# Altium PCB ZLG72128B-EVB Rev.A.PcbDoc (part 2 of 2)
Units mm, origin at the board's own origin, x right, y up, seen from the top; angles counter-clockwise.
Board outline 130 x 80 mm, 2 copper layers (Top Layer, Bottom Layer); 109 components, 70 nets, 433 pads, 399 vias.
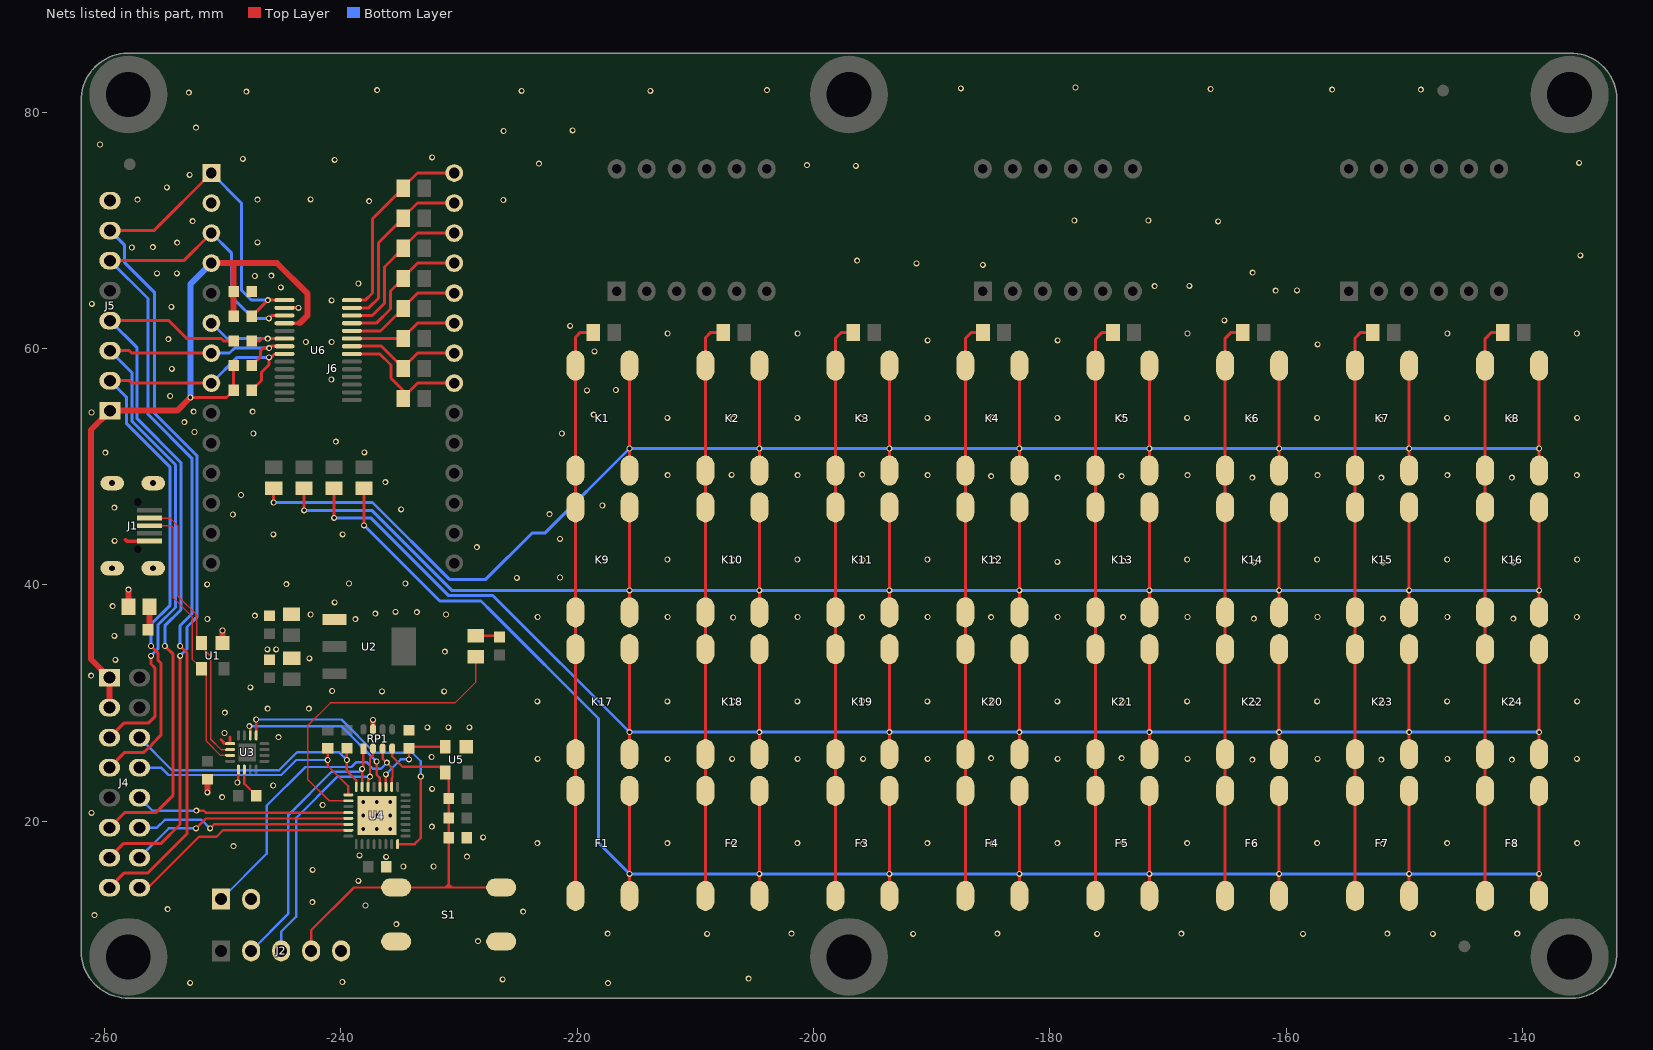
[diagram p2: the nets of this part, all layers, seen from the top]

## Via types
v1: diameter 0.508, hole 0.305, Top Layer to Bottom Layer, tented both sides, 399 vias

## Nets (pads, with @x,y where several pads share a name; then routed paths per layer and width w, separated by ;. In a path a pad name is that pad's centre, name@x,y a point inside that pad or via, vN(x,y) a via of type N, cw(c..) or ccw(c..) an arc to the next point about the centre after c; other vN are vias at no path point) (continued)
GND: C1.2 C2.1 C3.1 C4.2 C5.2 C7.1 C11.1 C12.1 J1.5 J1.6 J1.7 J1.8 J1.9 J2.5 J3.2 J5.8 J6.2 LED3.2 R7.1 RP1.7 S1.1 S1.4 U1.1 U2.1 U3.1 U3.13 U4.33 U5.1 U6.2 | length 10.3
  Top Layer w0.203: v1(-248.764,23.263) -248.676,23.351 U3.1@-248.676,24.353
  Top Layer w0.254: -250.161,26.883 -249.831,26.553 U3.13@-249.376,26.553 -249.376,27.128
  Top Layer w0.305: -258.238,43.811 -258.127,43.7 J1.5@-256.201,43.7 ; U6.2@-244.781,63.439 v1(-243.589,63.439)
  Top Layer w0.406: RP1.7@-237.289,27.765 v1(-237.289,28.565)
  Top Layer w0.508: LED3.2@-257.984,38.147 v1(-257.984,39.595) ; v1(-251.306,22.427) C5.2@-251.306,23.529 ; U1.1@-250.021,35.074 v1(-250.021,36.128)
  other v1: -217.399,6.274 -252.755,6.299 -239.878,6.375 -226.314,6.604 -205.486,6.655 -228.397,9.83 -208.997,10.447 -191.569,10.447 -175.997,10.447 -158.569,10.447 -147.569,10.447 -217.432,10.472 -201.86,10.472 -184.432,10.472 -168.86,10.472 -151.432,10.472 -140.432,10.472 -235.306,11.278 -260.858,12.04 -224.569,12.326 -254.66,12.548 -237.918,12.849 -242.414,13.128 -238.528,14.931 -242.388,15.871 -234.718,16.151 -232.152,16.151 -236.179,16.969 -229.333,16.989 -238.426,17.089 -249.098,17.882 -195.83,18.081 -184.832,18.081 -162.734,18.081 -151.812,18.081 -140.763,18.081 -206.752,18.106 -223.367,18.135 -212.367,18.135 -201.367,18.135 -190.367,18.135 -179.367,18.135 -168.367,18.135 -157.367,18.135 -146.367,18.135 -135.36,18.135 -173.783,18.208 -227.961,18.614 -238.096,19.326 -236.953,19.326 -235.81,19.326 -232.305,19.529 -238.096,20.469 -236.953,20.469 -235.81,20.469 -261.112,20.701 -241.554,21.361 -238.096,21.612 -236.953,21.612 -235.81,21.612 -250.063,22.022 -232.287,22.729 -245.745,23.012 -162.861,25.193 -151.939,25.193 -140.89,25.193 -223.342,25.272 -212.342,25.272 -206.879,25.269 -201.342,25.272 -195.805,25.269 -190.342,25.272 -179.342,25.272 -168.342,25.272 -157.342,25.272 -146.342,25.272 -135.385,25.272 -184.959,25.32 -173.91,25.32 -232.33,25.422 -245.284,27.098 -249.856,27.454 -232.686,27.936 -230.908,27.936 -229.13,27.936 -249.831,29.181 -246.198,29.511 -242.719,29.511 -162.795,29.976 -151.873,29.976 -140.824,29.976 -173.844,30.103 -206.778,30.121 -223.367,30.135 -212.367,30.135 -201.367,30.135 -195.881,30.146 -190.367,30.135 -184.832,30.146 -179.367,30.135 -168.367,30.135 -157.367,30.135 -146.367,30.135 -135.36,30.135 -236.521,30.984 -231.263,30.984 -240.737,31.01 -247.672,31.314 -261.137,32.309 -259.102,33.639 -242.668,33.766 -231.212,34.337 -246.224,34.54 -245.487,34.54 -259.178,35.683 -238.785,37.084 -251.304,37.106 -162.734,37.131 -151.812,37.131 -140.763,37.131 -206.803,37.233 -195.881,37.258 -184.959,37.258 -173.783,37.258 -223.342,37.272 -212.342,37.272 -201.342,37.272 -190.342,37.272 -179.342,37.272 -168.342,37.272 -157.342,37.272 -146.342,37.272 -135.385,37.272 -247.291,37.385 -242.566,37.487 -231.111,37.487 -237.08,37.563 -233.575,37.69 -235.378,37.715 -259.33,38.198 -240.538,38.506 -251.329,40.027 -244.624,40.052 -239.315,40.103 -234.54,40.103 -225.116,40.585 -221.459,40.611 -162.73,41.882 -151.808,41.882 -140.759,41.882 -179.367,41.932 -173.779,42.009 -184.705,42.084 -206.803,42.109 -195.844,42.103 -212.367,42.135 -201.367,42.135 -190.367,42.135 -168.367,42.135 -157.367,42.135 -146.367,42.135 -135.36,42.135 -228.495,43.176 -259.152,43.71 -221.459,43.887 -245.716,44.268 -239.848,44.268 -249.145,45.945 -222.348,45.97 -234.895,46.377 -259.178,46.529 -217.877,46.707 -248.459,47.596 -236.242,48.688 -179.342,49.069 -162.861,49.069 -151.939,49.069 -140.89,49.069 -184.959,49.196 -173.91,49.196 -212.342,49.272 -201.342,49.272 -190.342,49.272 -168.342,49.272 -157.342,49.272 -146.342,49.272 -135.385,49.272 -206.93,49.298 -195.881,49.323 -259.94,51.177 -238.02,51.203 -240.433,52.117 -247.418,52.803 -221.306,52.803 -252.396,52.93 -253.249,53.768 -162.922,53.976 -152,53.976 -140.951,53.976 -206.803,54.098 -195.971,54.099 -173.971,54.103 -212.367,54.135 -201.367,54.135 -190.367,54.135 -179.367,54.135 -168.367,54.135 -157.367,54.135 -146.367,54.135 -135.36,54.135 -184.832,54.149 -218.614,54.403 -261.112,54.585 -252.472,54.657 -247.468,54.657 -254.457,55.982 -219.173,56.46 -216.734,56.486 -240.814,57.375 -254.305,58.268 -218.538,59.762 -157.324,60.347 -242.973,60.55 -240.788,60.55 -190.342,60.688 -179.342,60.688 -254.61,60.782 -212.342,61.272 -201.342,61.272 -168.342,61.272 -146.342,61.272 -135.385,61.272 -220.595,61.921 -165.223,62.379 -254.356,63.525 -261.087,63.779 -240.788,64.08 -160.88,64.893 -159.076,64.919 -245.081,65.173 -171.116,65.274 -168.195,65.3 -238.528,65.503 -247.279,66.138 -245.894,66.163 -255.571,66.366 -253.895,66.366 -162.836,66.417 -185.67,67.078 -191.284,67.205 -196.313,67.433 -135.099,67.89 -257.705,68.551 -255.927,68.576 -253.869,68.957 -247.062,68.983 -165.757,70.761 -252.548,70.786 -177.923,70.837 -171.649,70.837 -237.613,72.462 -226.259,72.564 -257.222,72.589 -247.062,72.589 -242.566,72.615 -254.733,73.631 -252.802,74.698 -196.414,75.46 -200.555,75.51 -223.237,75.637 -135.2,75.714 -240.534,75.968 -248.307,76.044 -232.279,76.171 -260.397,77.263 -226.234,78.406 -220.392,78.457 -252.269,78.685 -252.88,81.66 -248.002,81.733 -224.71,81.81 -213.813,81.81 -236.927,81.86 -203.933,81.86 -156.105,81.911 -148.586,81.911 -166.392,81.962 -187.524,82.013 -177.822,82.089
I2C0_SCL: J4.7 J5.2 J6.8 R15.1 U6.8 | length 57.7
  Top Layer w0.254: J4.7@-259.595,24.52 -258.299,25.816 -256.688,25.816 -256.397,26.107 ccw(c-256.905,27.06) -255.952,26.552 -255.245,27.259 -255.245,33.376 -255.495,33.626 -255.495,34.235 v1(-256.079,34.82) ; J5.2@-259.543,57.273 -257.908,57.273 -257.705,57.07 J6.8@-250.963,57.07 ; R15.1@-247.551,56.46 -246.72,57.291 -246.72,57.995 -246.085,58.63 v1(-246.085,59.257) ; v1@-245.907,59.257 -245.625,59.539 U6.8@-244.781,59.539
  Bottom Layer w0.254: J5.2@-259.543,57.273 -258.162,55.892 -258.162,53.666 -254.453,49.958 -254.453,38.274 -256.079,36.648 v1(-256.079,34.82) ; J6.8@-250.963,57.07 -248.776,59.257 v1(-246.085,59.257)
I2C0_SDA: J4.5 J5.3 J6.7 R16.1 U6.7 | length 56.3
  Top Layer w0.254: J4.5@-259.595,27.06 -258.376,28.279 -256.302,28.279 -255.753,28.829 -255.753,32.969 -256.079,33.296 v1(-256.079,33.981) ; J5.3@-259.543,59.813 -257.913,59.813 -257.71,59.61 J6.7@-250.963,59.61 ; R16.1@-247.551,58.55 -246.808,59.293 -246.808,59.807 -246.579,60.036 v1(-246.078,60.036) -245.924,60.189 U6.7@-244.781,60.189
  Bottom Layer w0.254: J5.3@-259.543,59.813 -257.705,57.975 -257.705,53.856 -253.996,50.147 -253.996,38.085 -255.495,36.586 -255.495,34.566 v1(-256.079,33.981) ; J6.7@-250.963,59.61 -249.424,59.61 -248.999,60.036 v1(-246.078,60.036)
IIC/SPI: J4.15 J5.6 J6.3 U6.3 | length 81.5
  Top Layer w0.254: J4.15@-259.595,14.36 -258.338,15.617 -256.333,15.617 -253.031,18.919 -253.031,34.235 v1(-253.615,34.82) ; J5.6@-259.543,67.433 -253.3,67.433 J6.3@-250.963,69.77 ; v1(-246.097,62.556) -245.864,62.789 U6.3@-244.781,62.789
  Bottom Layer w0.254: J5.6@-259.543,67.433 -256.333,64.223 -256.333,54.424 -252.625,50.716 -252.625,37.516 -253.615,36.526 v1(-253.615,34.82) ; J6.3@-250.963,69.77 -249.246,68.053 -249.246,64.36 -247.443,62.556 v1(-246.097,62.556)
ISP: J3.1 RP1.3 U4.2 | length 25.2
  Top Layer w0.203: RP1.3@-236.477,26.139 -236.477,25.301 v1(-236.111,24.936) -235.632,24.456 -235.632,23.717 ; U4.2@-235.703,22.894 -235.703,23.646
  Bottom Layer w0.203: J3.1@-250.135,13.382 -246.275,17.243 -246.275,21.307 -243.004,24.577 -239.093,24.577 -238.68,24.99 -237.842,24.99 -237.283,24.431 -236.616,24.431 v1(-236.111,24.936)
J_NRST: C9.1 C11.2 J2.4 R6.1 RP1.4 S1.2 S1.3 U5.3 | length 35.9
  Top Layer w0.203: J2.4@-242.515,9.013 -242.515,10.766 -238.909,14.373 -237.715,14.373 ; -237.943,14.373 S1.3@-235.327,14.373 -230.882,14.373 ; RP1.4@-235.664,26.139 -235.664,25.479 -234.768,24.583 -231.657,24.583 U5.3@-231.174,24.101 -230.882,23.809 C9.1@-230.882,21.916 R6.1@-230.882,20.253 C11.2@-230.882,18.589 -230.882,14.779 -230.882,14.652 ; -231.162,14.373 -230.882,14.652 ; -230.603,14.373 -230.882,14.652 ; S1.2@-226.437,14.373 -230.882,14.373 ; -230.882,14.373 -230.882,14.652
KEY: J6.6 R17.2 U6.6 | length 8.3
  Top Layer w0.254: R17.2@-247.551,60.639 -246.878,60.639 -246.678,60.839 v1(-246.195,60.839) ; v1@-246.302,60.839 v1(-246.195,60.839) ; U6.6@-244.781,60.839 v1(-246.195,60.839)
  Bottom Layer w0.254: J6.6@-250.963,62.15 -249.652,60.839 v1(-246.195,60.839)
KEY_INT: J4.11 J5.4 R17.1 | length 61.2
  Top Layer w0.254: J4.11@-259.595,19.44 -258.325,20.71 -255.685,20.71 -254.203,22.192 -254.203,34.112 v1(-254.911,34.82) ; J5.4@-259.543,62.353 -254.555,62.353 -253.056,60.855 -250.135,60.855 -249.92,60.639 R17.1@-249.075,60.639
  Bottom Layer w0.254: J5.4@-259.543,62.353 -257.247,60.058 -257.247,54.045 -253.539,50.337 -253.539,37.895 -254.911,36.524 v1(-254.911,34.82)
LED0: LED0.2 U4.10 | length 26.6
  Top Layer w0.127: U4.10@-239.378,21.719 -240.997,21.719 -242.82,23.542 -242.82,28.063 -240.89,29.994 -230.349,29.994 -228.571,31.772 LED0.2@-228.571,33.905
NetF1_1: F1.1 F1.4 F2.1 F2.4 F3.1 F3.4 F4.1 F4.4 F5.1 F5.4 F6.1 F6.4 F7.1 F7.4 F8.1 F8.4 R31.2 | length 193.3
  Top Layer w0.254: v1(-238.045,45.03) R31.2@-238.045,48.155 -238.045,46.961 ; F1.4@-215.578,13.664 v1(-215.578,15.533) F1.1@-215.578,22.554 ; F2.4@-204.578,13.664 v1(-204.578,15.533) F2.1@-204.578,22.554 ; F3.4@-193.578,13.664 v1(-193.578,15.533) F3.1@-193.578,22.554 ; F4.4@-182.578,13.664 v1(-182.578,15.533) F4.1@-182.578,22.554 ; F5.4@-171.578,13.664 v1(-171.578,15.533) F5.1@-171.578,22.554 ; F6.4@-160.578,13.664 v1(-160.578,15.533) F6.1@-160.578,22.554 ; F7.4@-149.578,13.664 v1(-149.578,15.533) F7.1@-149.578,22.554 ; F8.4@-138.578,13.664 v1(-138.578,15.533) F8.1@-138.578,22.554
  Bottom Layer w0.254: v1(-238.045,45.03) -231.633,38.618 -228.153,38.618 -227.199,37.664 -218.208,28.673 -218.208,18.163 v1(-215.578,15.533) v1(-204.578,15.533) v1(-193.578,15.533) v1(-182.578,15.533) v1(-171.578,15.533) v1(-160.578,15.533) v1(-149.578,15.533) v1(-138.578,15.533)
NetF1_2: F1.2 F1.3 K1.2 K1.3 K9.2 K9.3 K17.2 K17.3 R20.1 | length 49
  Top Layer w0.254: F1.3@-220.15,13.664 F1.2@-220.15,22.554 K17.3@-220.15,25.664 K17.2@-220.15,34.554 K9.3@-220.15,37.664 K9.2@-220.15,46.554 K1.3@-220.15,49.664 K1.2@-220.15,58.554 -220.15,60.956 -219.743,61.363 R20.1@-218.651,61.363
NetF2_2: F2.2 F2.3 K2.2 K2.3 K10.2 K10.3 K18.2 K18.3 R21.1 | length 49.7
  Top Layer w0.254: F2.3@-209.15,13.664 F2.2@-209.15,22.554 K18.3@-209.15,25.664 K18.2@-209.15,34.554 K10.3@-209.15,37.664 K10.2@-209.15,46.554 K2.3@-209.15,49.664 K2.2@-209.15,58.554 ; K2.2@-209.15,59.048 K2.2@-209.15,58.554 ; -209.15,60.51 -209.15,60.22 ; R21.1@-207.651,61.363 -208.704,61.363 -209.15,60.917 -209.15,60.22 ; K2.2@-209.15,58.554 -209.15,60.22
NetF3_2: F3.2 F3.3 K3.2 K3.3 K11.2 K11.3 K19.2 K19.3 R22.1 | length 49.5
  Top Layer w0.254: F3.3@-198.15,13.664 F3.2@-198.15,22.554 K19.3@-198.15,25.664 K19.2@-198.15,34.554 K11.3@-198.15,37.664 K11.2@-198.15,46.554 K3.3@-198.15,49.664 K3.2@-198.15,58.554 ; K3.2@-198.15,59.11 K3.2@-198.15,58.554 ; R22.1@-196.652,61.363 -197.639,61.363 -198.15,60.852 K3.2@-198.15,58.554
NetF4_2: F4.2 F4.3 K4.2 K4.3 K12.2 K12.3 K20.2 K20.3 R23.1 | length 49.5
  Top Layer w0.254: F4.3@-187.15,13.664 F4.2@-187.15,22.554 K20.3@-187.15,25.664 K20.2@-187.15,34.554 K12.3@-187.15,37.664 K12.2@-187.15,46.554 K4.3@-187.15,49.664 K4.2@-187.15,58.554 ; K4.2@-187.15,59.121 K4.2@-187.15,58.554 ; R23.1@-185.652,61.363 -186.624,61.363 -187.15,60.837 K4.2@-187.15,58.554
NetF5_2: F5.2 F5.3 K5.2 K5.3 K13.2 K13.3 K21.2 K21.3 R24.1 | length 48.8
  Top Layer w0.254: F5.3@-176.15,13.664 F5.2@-176.15,22.554 K21.3@-176.15,25.664 K21.2@-176.15,34.554 K13.3@-176.15,37.664 K13.2@-176.15,46.554 K5.3@-176.15,49.664 K5.2@-176.15,58.554 -176.15,60.765 -175.552,61.363 R24.1@-174.652,61.363
NetF6_2: F6.2 F6.3 K6.2 K6.3 K14.2 K14.3 K22.2 K22.3 R25.1 | length 49.2
  Top Layer w0.254: F6.3@-165.15,13.664 F6.2@-165.15,22.554 K22.3@-165.15,25.664 K22.2@-165.15,34.554 K14.3@-165.15,37.664 K14.2@-165.15,46.554 K6.3@-165.15,49.664 K6.2@-165.15,58.554 K6.2@-165.15,58.797 ; K6.2@-165.15,59.093 K6.2@-165.15,58.797 ; R25.1@-163.653,61.363 -164.647,61.363 -165.15,60.86 K6.2@-165.15,58.797
NetF7_2: F7.2 F7.3 K7.2 K7.3 K15.2 K15.3 K23.2 K23.3 R26.1 | length 49.3
  Top Layer w0.254: F7.3@-154.15,13.664 F7.2@-154.15,22.554 K23.3@-154.15,25.664 K23.2@-154.15,34.554 K15.3@-154.15,37.664 K15.2@-154.15,46.554 K7.3@-154.15,49.664 K7.2@-154.15,58.554 ; K7.2@-154.15,58.97 K7.2@-154.15,58.554 ; R26.1@-152.653,61.363 -153.683,61.363 -154.15,60.896 K7.2@-154.15,58.554
NetF8_2: F8.2 F8.3 K8.2 K8.3 K16.2 K16.3 K24.2 K24.3 R27.1 | length 48.9
  Top Layer w0.254: F8.3@-143.15,13.664 F8.2@-143.15,22.554 K24.3@-143.15,25.664 K24.2@-143.15,34.554 K16.3@-143.15,37.664 K16.2@-143.15,46.554 K8.3@-143.15,49.664 K8.2@-143.15,58.554 -143.15,60.831 -142.618,61.363 R27.1@-141.653,61.363
NetK1_1: K1.1 K1.4 K2.1 K2.4 K3.1 K3.4 K4.1 K4.4 K5.1 K5.4 K6.1 K6.4 K7.1 K7.4 K8.1 K8.4 R28.2 | length 187.2
  Top Layer w0.254: v1(-245.69,46.961) R28.2@-245.69,48.155 ; K1.4@-215.578,49.664 v1(-215.578,51.533) K1.1@-215.578,58.554 K1.1@-215.578,59.037 ; K2.4@-204.578,49.664 v1(-204.578,51.533) K2.1@-204.578,58.554 ; K3.4@-193.578,49.664 v1(-193.578,51.533) K3.1@-193.578,58.554 ; K4.4@-182.578,49.664 v1(-182.578,51.533) K4.1@-182.578,58.554 ; K5.4@-171.578,49.664 v1(-171.578,51.533) K5.1@-171.578,58.554 ; K6.4@-160.578,49.664 v1(-160.578,51.533) K6.1@-160.578,58.554 ; K7.4@-149.578,49.664 v1(-149.578,51.533) K7.1@-149.578,58.554 ; K8.4@-138.578,49.664 v1(-138.578,51.533) K8.1@-138.578,58.554
  Bottom Layer w0.254: v1(-245.69,46.961) -237.334,46.961 -230.831,40.458 -227.733,40.458 -223.821,44.37 -222.74,44.37 v1(-215.578,51.533) v1(-204.578,51.533) v1(-193.578,51.533) v1(-182.578,51.533) v1(-171.578,51.533) v1(-160.578,51.533) v1(-149.578,51.533) v1(-138.578,51.533)
NetK9_1: K9.1 K9.4 K10.1 K10.4 K11.1 K11.4 K12.1 K12.4 K13.1 K13.4 K14.1 K14.4 K15.1 K15.4 K16.1 K16.4 R29.2 | length 180.3
  Top Layer w0.254: v1(-243.122,46.3) R29.2@-243.122,48.155 ; K9.4@-215.578,37.664 v1(-215.578,39.533) K9.1@-215.578,46.554 ; K10.4@-204.578,37.664 v1(-204.578,39.533) K10.1@-204.578,46.554 ; K11.4@-193.578,37.664 v1(-193.578,39.533) K11.1@-193.578,46.554 ; K12.4@-182.578,37.664 v1(-182.578,39.533) K12.1@-182.578,46.554 ; K13.4@-171.578,37.664 v1(-171.578,39.533) K13.1@-171.578,46.554 ; K14.4@-160.578,37.664 v1(-160.578,39.533) K14.1@-160.578,46.554 ; K15.4@-149.578,37.664 v1(-149.578,39.533) K15.1@-149.578,46.554 ; K16.4@-138.578,37.664 v1(-138.578,39.533) K16.1@-138.578,46.554
  Bottom Layer w0.254: v1(-243.122,46.3) -237.392,46.3 -230.624,39.533 v1(-215.578,39.533) v1(-204.578,39.533) v1(-193.578,39.533) v1(-182.578,39.533) v1(-171.578,39.533) v1(-160.578,39.533) v1(-149.578,39.533) v1(-138.578,39.533)
NetK17_1: K17.1 K17.4 K18.1 K18.4 K19.1 K19.4 K20.1 K20.4 K21.1 K21.4 K22.1 K22.4 K23.1 K23.4 K24.1 K24.4 R30.2 | length 184.3
  Top Layer w0.254: v1(-240.578,45.665) R30.2@-240.578,48.155 -240.578,46.961 ; K17.4@-215.578,25.664 v1(-215.578,27.533) K17.1@-215.578,34.554 ; K18.4@-204.578,25.664 v1(-204.578,27.533) K18.1@-204.578,34.554 ; K19.4@-193.578,25.664 v1(-193.578,27.533) K19.1@-193.578,34.554 ; K20.4@-182.578,25.664 v1(-182.578,27.533) K20.1@-182.578,34.554 ; K21.4@-171.578,25.664 v1(-171.578,27.533) K21.1@-171.578,34.554 ; K22.4@-160.578,25.664 v1(-160.578,27.533) K22.1@-160.578,34.554 ; K23.4@-149.578,25.664 v1(-149.578,27.533) K23.1@-149.578,34.554 ; K24.4@-138.578,25.664 v1(-138.578,27.533) K24.1@-138.578,34.554
  Bottom Layer w0.254: v1(-240.578,45.665) -237.475,45.665 -230.885,39.076 -227.12,39.076 v1(-215.578,27.533) v1(-204.578,27.533) v1(-193.578,27.533) v1(-182.578,27.533) v1(-171.578,27.533) v1(-160.578,27.533) v1(-149.578,27.533) v1(-138.578,27.533)
NetLED0_1: LED0.1 R34.1 | length 2
  Top Layer w0.203: LED0.1@-228.571,35.683 -226.691,35.683 R34.1@-226.59,35.582
NetLED3_1: LED3.1 R3.2 | length 2
  Top Layer w0.508: R3.2@-256.333,36.191 -256.206,36.318 LED3.1@-256.206,38.147
NetR4_2: R4.2 U3.2 | length 2.6
  Top Layer w0.203: U3.2@-248.176,24.353 -248.176,23.151 R4.2@-247.168,22.143
NRST: J4.13 J5.7 J6.1 R8.1 U6.1 | length 88.5
  Top Layer w0.254: J4.13@-259.595,16.9 -258.376,18.119 -255.203,18.119 -253.615,19.707 v1(-253.615,33.981) ; J5.7@-259.543,69.973 -255.84,69.973 J6.1@-250.963,74.85 ; R8.1@-247.551,62.728 v1(-246.19,64.089) U6.1@-244.781,64.089
  Bottom Layer w0.254: J5.7@-259.543,69.973 -258.3,68.73 -258.3,67.268 -255.8,64.768 -255.8,54.537 -252.167,50.905 -252.167,37.283 -253.031,36.42 -253.031,34.566 v1(-253.615,33.981) ; J6.1@-250.963,74.85 -248.434,72.321 -248.434,64.944 -247.579,64.089 v1(-246.19,64.089)
PIO0_15: J4.16 U4.15 | length 20.4
  Top Layer w0.203: J4.16@-257.755,14.36 J4.16@-257.055,14.36 -256.32,14.36 -252.015,18.665 -250.542,18.665 -249.988,19.219 U4.15@-239.378,19.219
PIO0_24: J4.12 U4.14 | length 18.4
  Top Layer w0.203: v1(-251.075,19.376) -250.733,19.719 U4.14@-239.378,19.719
  Bottom Layer w0.203: J4.12@-257.055,19.44 -255.573,19.44 -254.9,20.113 -251.812,20.113 v1(-251.075,19.376)
PIO0_25: J4.14 U4.13 | length 19.1
  Top Layer w0.203: v1(-252.269,19.376) -251.427,20.219 U4.13@-239.378,20.219
  Bottom Layer w0.203: J4.14@-257.055,16.9 -254.579,19.376 v1(-252.269,19.376)
PIO0_26: J4.10 U4.12 | length 18.2
  Top Layer w0.203: v1(-252.244,20.875) -251.587,20.875 -251.431,20.719 U4.12@-239.378,20.719
  Bottom Layer w0.203: J4.10@-257.055,21.98 -255.95,20.875 v1(-252.244,20.875)
R\E\S\E\T\: R7.2 U4.3 U5.2 | length 7.6
  Top Layer w0.203: U4.3@-236.203,22.894 v1(-236.203,23.948) ; v1@-234.241,25.244 R7.2@-234.241,26.171 -234.127,26.285 U5.2@-231.174,26.285
  Bottom Layer w0.203: v1(-236.203,23.948) -234.926,25.225 v1(-234.241,25.225)
SCL: J4.8 R36.1 U4.9 | length 21.4
  Top Layer w0.203: R36.1@-241.118,26.158 v1(-241.118,25.168) -241.118,24.685 -239.378,22.944 U4.9@-239.378,22.219
  Bottom Layer w0.203: J4.8@-257.055,24.52 -255.22,24.52 -254.598,23.898 -245.055,23.898 -243.785,25.168 v1(-241.118,25.168)
SDA: J4.6 R35.1 U4.8 | length 23.5
  Top Layer w0.203: v1@-239.493,25.345 -239.493,25.625 ; R35.1@-239.493,26.158 -239.493,25.625 ; U4.8@-238.703,22.894 -238.703,23.438 -239.493,24.228 v1(-239.493,25.168) -239.493,25.625
  Bottom Layer w0.203: J4.6@-257.055,27.06 -254.299,24.304 -245.233,24.304 -243.709,25.828 -240.153,25.828 v1(-239.493,25.168)
SEG0: J6.21 R19.1 U6.21 | length 11.8
  Top Layer w0.254: U6.21@-239.081,59.539 -236.704,59.539 -235.759,58.594 -235.759,57.483 -234.743,56.467 R19.1@-234.743,55.823 ; R19.1@-234.743,55.762 R19.1@-234.743,55.823 ; J6.21@-230.41,57.07 -233.496,57.07 R19.1@-234.743,55.823
SEG1: J6.22 R18.1 U6.22 | length 10
  Top Layer w0.254: U6.22@-239.081,60.189 -236.566,60.189 R18.1@-234.743,58.366 ; R18.1@-234.743,58.305 R18.1@-234.743,58.366 ; J6.22@-230.41,59.61 -233.499,59.61 R18.1@-234.743,58.366
SEG2: J6.23 R14.1 U6.23 | length 10
  Top Layer w0.254: U6.23@-239.081,60.839 R14.1@-234.753,60.839 ; R14.1@-234.743,60.849 -234.743,60.91 -233.503,62.15 -232.355,62.15 ; -233.096,62.15 -232.355,62.15 ; J6.23@-230.41,62.15 -232.025,62.15 -232.355,62.15
SEG3: J6.24 R13.1 U6.24 | length 10
  Top Layer w0.254: U6.24@-239.081,61.489 -236.646,61.489 R13.1@-234.743,63.392 -234.743,63.453 -233.506,64.69 -232.432,64.69 J6.24@-230.41,64.69
SEG4: J6.25 R12.1 U6.25 | length 11.7
  Top Layer w0.254: U6.25@-239.081,62.139 -237.014,62.139 -235.81,63.344 -235.81,64.868 R12.1@-234.743,65.935 -234.743,65.996 -233.509,67.23 J6.25@-230.41,67.23
SEG5: J6.26 R11.1 U6.26 | length 13.4
  Top Layer w0.254: U6.26@-239.081,62.789 -237.355,62.789 -236.318,63.826 -236.318,66.904 R11.1@-234.743,68.478 -234.743,68.539 -233.512,69.77 J6.26@-230.41,69.77
SEG6: J6.27 R10.1 U6.27 | length 15.1
  Top Layer w0.254: U6.27@-239.081,63.439 -237.645,63.439 -236.826,64.258 -236.826,68.939 R10.1@-234.743,71.022 ; R10.1@-234.743,71.083 -233.516,72.31 J6.27@-230.41,72.31
SEG7: J6.28 R9.1 U6.28 | length 16.8
  Top Layer w0.254: U6.28@-239.081,64.089 -237.935,64.089 -237.334,64.69 -237.334,70.974 R9.1@-234.743,73.565 -234.743,73.626 -233.519,74.85 J6.28@-230.41,74.85
SWD_CLK: J2.3 RP1.2 U4.6 | length 22.9
  Top Layer w0.203: U4.6@-237.703,22.894 -237.703,23.478 -237.543,23.637 v1(-237.543,23.764) -237.543,25.32 -237.289,25.574 RP1.2@-237.289,26.139
  Bottom Layer w0.203: J2.3@-245.055,9.013 -245.055,10.639 -243.785,11.909 -243.785,20.265 -240.287,23.764 v1(-237.543,23.764)
SWD_IO: J2.2 RP1.1 U4.7 | length 24
  Top Layer w0.203: U4.7@-238.203,22.894 v1(-238.203,24.426) -238.102,24.526 RP1.1@-238.102,26.139
  Bottom Layer w0.203: J2.2@-247.595,9.013 -244.446,12.163 -244.446,20.519 -240.795,24.171 -238.458,24.171 v1(-238.203,24.426)
UART_RXD: U3.9 U4.24 | length 25.4
  Top Layer w0.203: U3.9@-247.176,27.253 v1(-247.176,28.597) ; U4.24@-235.203,18.044 -233.764,18.044 -233.244,18.564 v1(-233.244,23.771)
  Bottom Layer w0.203: v1(-247.176,28.597) -239.959,28.597 -237.146,25.784 -233.962,25.784 -233.244,25.066 v1(-233.244,23.771)
UART_TXD: U3.10 U4.4 | length 15.7
  Top Layer w0.203: v1(-247.752,28.034) -247.676,27.958 U3.10@-247.676,27.253 ; v1(-236.978,25.041) -236.978,23.919 -236.703,23.644 U4.4@-236.703,22.894
  Bottom Layer w0.203: v1(-247.752,28.034) -240.814,28.034 ; -240.175,28.034 -240.814,28.034 ; v1(-236.978,25.041) -239.971,28.034 -240.814,28.034
USB_N: J1.2 U1.2 U3.14 | length 23.7
  Top Layer w0.127: J1.2@-256.001,45.65 -254.463,45.65 -253.793,44.98 -253.793,39.036 -252.193,37.436 -252.193,35.112 -251.799,34.718 -251.024,33.943 -251.024,26.926 -250.151,26.053 U3.14@-249.376,26.053
USB_P: J1.3 U1.3 U3.15 | length 23.9
  Top Layer w0.127: J1.3@-256.001,45 -254.352,45 -254.174,44.822 -254.174,38.878 -252.574,37.278 -252.574,36.648 ; -252.574,36.922 -252.574,36.648 ; U3.15@-249.376,25.553 -250.19,25.553 -251.405,26.768 -251.405,32.496 U1.3@-251.799,32.889 -252.574,33.664 -252.574,36.648
VCC: C12.2 J4.1 J4.3 J5.1 J6.4 R8.2 R15.2 R16.2 U6.4 | length 69.8
  Top Layer w0.254: v1(-252.752,55.851) -249.685,55.851 R15.2@-249.075,56.46 ; R15.2@-249.075,56.283 R15.2@-249.075,56.46 ; R16.2@-249.075,58.55 R15.2@-249.075,56.46
  Top Layer w0.305: U6.4@-244.781,62.139 -243.492,62.139
  Top Layer w0.508: J4.3@-259.595,29.6 J4.1@-259.595,32.14 -261.159,33.704 -261.159,53.117 J5.1@-259.543,54.733 -253.869,54.733 v1(-252.752,55.851) ; J6.4@-250.963,67.23 -249.075,67.23 ; R8.2@-249.075,62.728 C12.2@-249.075,64.817 -249.075,67.23 ; -243.492,62.139 -242.82,62.81 -242.82,64.639 -245.411,67.23 -249.075,67.23
  Bottom Layer w0.508: v1(-252.752,55.851) -252.752,65.441 J6.4@-250.963,67.23
pads on no net: HOLE1.1 HOLE2.1 HOLE3.1 HOLE4.1 HOLE5.1 HOLE6.1 J1.0 J1.4 MARK1.0 MARK2.0 MARK3.0 U3.3 U3.4 U3.5 U3.6 U3.7 U3.8 U3.11 U3.12 U3.17 U4.1 U4.5 U4.11 U4.16 U4.17 U4.18 U4.20 U4.21 U4.22 U4.23 U4.25 U4.26 U4.27 U4.28 U4.29 U4.30 U4.31 U4.32

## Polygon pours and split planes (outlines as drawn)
GND on Top Layer "gnd" (solid, remove dead copper, pour order 1000): -261.547,5.453 -261.547,84.547 -132.453,84.547 -132.453,5.453
GND on Bottom Layer "gnd" (solid, remove dead copper, pour order 1001): -261.547,5.453 -261.547,84.547 -132.453,84.547 -132.453,5.453

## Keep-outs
Keep-Out Layer:
  lines w0.127: -135.85,84.999 cw(c-135.85,81.149) -132,81.149 -132,8.85 cw(c-135.85,8.85) -135.85,5 -258.15,5 cw(c-258.15,8.85) -262,8.85 -262,81.15 cw(c-258.15,81.15) -258.15,85 -135.85,85

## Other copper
Top Layer:
  pour cut-out: -244.584,47.199 -244.584,50.51 -239.151,50.51 -239.151,47.199
  pour cut-out: -229.269,41.83 -229.269,44.37 -232.101,44.37 -232.101,41.83
  pour cut-out: -221.143,53.757 -221.143,54.378 -220.668,54.378 -220.668,53.757 -221.143,53.757
  region net GND: -246.859,33.194 -246.96,33.296 -246.96,34.388 -246.503,34.845 -245.36,34.845 -244.979,34.464 -242.973,34.464 -242.668,34.159 -242.668,33.373 -242.847,33.194
  region net 3.3V: -241.347,35.302 -238.223,35.302 -236.546,36.979 -233.143,36.979 -232.94,36.775 -232.94,33.016 -233.219,32.737 -236.699,32.737 -238.121,34.159 -241.271,34.159 -241.449,34.337 -241.449,35.201
Bottom Layer:
  pour cut-out: -221.7,53.285 -221.7,52.473 -222.856,52.473 -222.856,53.285
  pour cut-out: -155.825,66.051 -144.224,66.051 -144.224,63.667 -155.825,63.667
  pour cut-out: -154.682,73.988 -141.981,73.988 -141.981,76.42 -154.682,76.42
  pour cut-out: -203.958,76.42 -217.606,76.42 -217.606,73.988 -203.958,73.988

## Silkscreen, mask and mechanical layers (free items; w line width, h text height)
Top Overlay:
  region: -14.421,3.961 -11.5,2.5 -14.421,1.04
  region: -21.152,3.399 -14.421,3.399 -14.421,1.592 -21.152,1.592 -21.152,1.897 -14.897,1.897 -14.897,3.094 -20.517,3.094 -20.517,1.897 -21.152,1.897
  text "ZLG72128B-EVB" at -231.289,82.064 h1.07
  text "230815 Rev.A" at -230.251,79.883 h1.07
  text "P/N:13.01.06949" at -231.013,78.105 h1.07
  text "GND" at -257.81,71.907 h0.89
  text "NRST" at -257.81,69.367 h0.89
  text "IIC/SPI" at -257.81,66.929 h0.89
  text "A4(CS)" at -257.81,64.186 h0.89
  text "INT" at -257.81,61.747 h0.89
  text "SDA" at -257.81,59.233 h0.89
  text "SCL" at -257.81,56.667 h0.89
  text "VCC" at -257.81,54.153 h0.89
  text "3V3" at -255.346,31.572 h0.89
  text "5V" at -255.346,29.032 h0.89
  text "SDA" at -255.346,26.492 h0.89
  text "SCL" at -255.346,24.003 h0.89
  text "A4(CS)" at -255.346,21.463 h0.89
  text "INT" at -255.346,18.999 h0.89
  text "NRST" at -255.346,16.358 h0.89
  text "ISP" at -251.024,15.135 h1.02
  text "GND" at -248.662,15.109 h1.02
  text "IIC/SPI" at -255.346,13.691 h0.89
  text "3V3" at -251.405,10.639 h1.02
  text "GND" at -240.839,10.639 h1.02
  text "CLK" at -246.503,10.613 h1.02
  text "RST" at -243.633,10.613 h1.02
  text "IO" at -248.053,10.588 h1.02
  text "SMT A" at -20.517,1.916 h2.29
Bottom Overlay:
  region: -234.3,76.5 -234.3,76.48 -234.315,76.443 -234.343,76.415 -234.38,76.4 -234.4,76.4 -249.2,76.4 -249.22,76.4 -249.257,76.415 -249.285,76.443 -249.3,76.48 -249.3,76.5 -249.3,81.3 -249.3,81.32 -249.285,81.357 -249.257,81.385 -249.22,81.4 -249.2,81.4 -234.4,81.4 -234.38,81.4 -234.343,81.385 -234.315,81.357 -234.3,81.32 -234.3,81.3
  lines w0.3: -258.325,13.09 -258.325,33.41
Mechanical 1:
  circle w0.025: c-6.35,167.499 r1
  circle w0.025: c-255.65,167.499 r1
  circle w0.025: c-255.65,2.5 r1
  circle w0.025: c-6.35,2.5 r1
  lines w0.025: -258.15,5 -258.15,2 ccw(c-256.15,2) -256.15,0 -5.85,0 ccw(c-5.85,2) -3.85,2 -3.85,5 -3.81,4.96 ; -258.15,164.999 -258.15,167.999 cw(c-256.15,167.999) -256.15,169.999 -5.85,169.999 cw(c-5.85,167.999) -3.85,167.999 -3.85,164.999 ; -136.5,5 ccw(c-136.5,4.25) -136.5,3.5 -125.5,3.5 ccw(c-125.5,4.25) -125.5,5 ; -136.5,164.999 cw(c-136.5,165.749) -136.5,166.499 -125.5,166.499 cw(c-125.5,165.749) -125.5,164.999
  lines w0.127: 1.357,4.365 -0.04,5 ; 1.357,5.635 -0.04,5 ; 1.357,84.365 -0.04,85 ; 1.357,85.635 -0.04,85 ; 1.357,164.364 -0.04,164.999 ; 1.357,165.634 -0.04,164.999 ; 4.532,5 -0.04,5 ; 4.532,85 -0.04,85 ; 4.532,164.999 -0.04,164.999 ; -258.15,85 cw(c-258.15,88.85) -262,88.85 -262,161.15 cw(c-258.15,161.15) -258.15,165 -135.85,165 cw(c-135.85,161.149) -132,161.149 -132,88.85 cw(c-135.85,88.85) -135.85,85 -258.15,85 ; -258.15,85 ccw(c-258.15,81.15) -262,81.15 -262,8.85 ccw(c-258.15,8.85) -258.15,5 -135.85,5 ccw(c-135.85,8.85) -132,8.85 -132,81.149 ccw(c-135.85,81.149) -135.85,84.999 -258.15,85 ; -126.15,85 ccw(c-126.15,81.15) -130,81.15 -130,8.85 ccw(c-126.15,8.85) -126.15,5 -3.85,5 ccw(c-3.85,8.85) 0,8.85 0,81.149 ccw(c-3.85,81.149) -3.85,84.999 ; -126.15,85 cw(c-126.15,88.85) -130,88.85 -130,161.15 cw(c-126.15,161.15) -126.15,165 -3.85,164.999 cw(c-3.85,161.149) 0,161.149 0,88.85 cw(c-3.85,88.85) -3.85,85 ; -126.15,85 -3.85,84.999 ; -126.15,85 -3.85,85
  text "VCUT" at 5.167,164.237 h1.52
  text "F" at -255.165,141.744 h12.7
  text "F" at -123.165,141.743 h12.7
  text "VCUT" at 5.167,84.238 h1.52
  text "F" at -255.165,61.744 h12.7
  text "F" at -123.165,61.743 h12.7
  text "VCUT" at 5.167,4.238 h1.52
Mechanical 2:
  drawing of 633 lines, arcs and shapes, not listed
  text "PCB加工工艺要求" at 70.077,116.705 h7.11
  text "mm x" at 49.681,111.981 h2.54
  text "mm" at 65.175,111.981 h2.54
  text "262" at 41.172,111.752 h2.54
  text "170" at 56.666,111.752 h2.54
  text "IPC-600  IPC-6011/12最新版本" at 94.588,111.727 h2.54
  text "IPC-Ⅱ" at 138.149,111.701 h2.54
  text "IPC-Ⅲ" at 150.849,111.701 h2.54
  text "尺寸" at 27.118,111.273 h3.81
  text "验收标准" at 77.918,111.273 h3.81
  text "FR4 TG140" at 45.058,106.647 h2.54
  text "FR4 TG170" at 67.918,106.647 h2.54
  text "生益有胶材料" at 90.778,106.647 h2.54
  text "MEGTRON6" at 113.638,106.647 h2.54
  text "其他：" at 136.498,106.647 h2.54
  text "板材" at 27.082,106.188 h3.81
  text "单面" at 45.058,101.567 h2.54
  text "2" at 62.838,101.567 h2.54
  text "4" at 80.618,101.567 h2.54
  text "6" at 98.398,101.567 h2.54
  text "8" at 116.178,101.567 h2.54
  text "10" at 133.958,101.567 h2.54
  text "板层" at 27.082,101.102 h3.81
  text "0.4mm" at 45.058,96.487 h2.54
  text "0.6mm" at 59.028,96.487 h2.54
  text "0.8mm" at 72.998,96.487 h2.54
  text "1.0mm" at 86.968,96.487 h2.54
  text "1.2mm" at 100.938,96.487 h2.54
  text "1.4mm" at 114.908,96.487 h2.54
  text "1.6mm" at 128.878,96.487 h2.54
  text "1.8mm" at 142.848,96.487 h2.54
  text "2.0mm" at 156.818,96.487 h2.54
  text "板厚" at 27.082,96.017 h3.81
  text "0.5OZ" at 76.3,91.407 h2.54
  text "1OZ" at 89,91.407 h2.54
  text "2OZ" at 101.7,91.407 h2.54
  text "（完成铜厚）" at 50.984,91.083 h3.3
  text "外层" at 43.967,90.924 h3.81
  text "铜厚" at 27.078,90.891 h3.81
  text "白色" at 56.488,86.327 h2.54
  text "其他：" at 74.268,86.327 h2.54
  text "丝印颜色" at 27.078,85.831 h3.81
  text "绿色" at 56.488,81.247 h2.54
  text "黑色" at 74.268,81.247 h2.54
  text "红色" at 92.048,81.247 h2.54
  text "蓝色" at 109.828,81.247 h2.54
  text "黄色" at 127.608,81.247 h2.54
  text "其他：" at 145.388,81.247 h2.54
  text "（亮光）" at 40.803,80.927 h3.3
  text "阻焊颜色" at 27.078,80.746 h3.81
  text "沉镍金 （金厚≥0.05um，镍厚≥3um）" at 56.869,76.319 h2.54
  text "无铅喷锡" at 109.828,76.167 h2.54
  text "电镀镍金" at 127.735,76.167 h2.54
  text "光板" at 145.388,76.167 h2.54
  text "其它" at 158.596,76.167 h2.54
  text "表面处理工艺" at 27.078,75.635 h3.81
  text "无" at 56.488,71.112 h2.54
  text "按键镀硬金" at 67.156,71.112 h2.54
  text "金手指" at 85.444,71.112 h2.54
  text "半孔工艺" at 102.97,71.112 h2.54
  text "FPCB补强" at 120.496,71.112 h2.54
  text "特殊工艺" at 27.078,70.575 h3.81
  text "树脂塞孔" at 123.417,65.778 h2.54
  text "电镀填孔" at 140.943,65.778 h2.54
  text "是，但双面开窗除外" at 56.488,65.753 h2.54
  text "否" at 85.571,65.753 h2.54
  text "按文件" at 103.351,65.753 h2.54
  text "是否阻焊塞孔" at 27.082,65.479 h3.81
  text "非拼板" at 56.488,60.927 h2.54
  text "拼板" at 74.268,60.927 h2.54
  text "Ver 22.10.31" at 147.166,60.698 h3.05
  text "交货方式" at 27.078,60.419 h3.81
  text "Gerber输出：英制、相对零点、抑制前导零、精度2:5" at 27.151,55.999 h3.05
  text "副边" at 149.452,53.84 h2.03
  text "NC Drill输出：英制、相对零点、抑制前导零、精度2:4" at 27.151,52.443 h3.05
  text "其他说明" at 27.024,47.998 h3.81
  text "桥连处不能添加铜皮" at 143.102,44.696 h2.03
  text "1." at 26.262,44.569 h3.05
  text "*.GM1 层为外形铣边；若有工艺副边，请在副边上增加整块平衡铜，" at 29.564,44.569 h3.05
  text "禁止使用方块状、点状图形，防机器误识别。但类似右图所示的桥连处，禁止添加平衡铜" at 29.437,41.648 h3.05
  text "2." at 26.259,38.473 h3.05
  text "请用供应商UL认证号，防火等级，CTI等级，生产周期替换板上的UR标识，且保持其位置、方向一致," at 29.564,38.473 h3.05
  text "若板内无，可在工艺副边添加; 禁止添加文件中不存在的元素，包括供应商LOGO、无铅、光学基准点等" at 29.564,35.18 h3.05
  text "R" at 156.335,32.771 h0.64
  text "3." at 26.262,31.869 h3.05
  text "若焊盘开窗与丝印油冲突，焊盘处需将丝印油掏开，不允许上盘" at 29.564,31.869 h3.05
  text "94V-0" at 158.113,31.361 h1.17
  text "标识样式>>>" at 139.038,30.345 h2.54
  text "CTI>=175" at 154.151,29.202 h2.2
  text "4." at 26.262,28.44 h3.05
  text "若存在5X15或4.4X6.6mm丝印白油块，其为激光打标用，需完整及平整；若无则忽略" at 29.564,28.44 h3.05
  text "5." at 26.262,25.011 h3.05
  text "若存在V-CUT，无特别说明时，须为双面V-CUT，角度30（+-5°），余量按以下表格执行" at 29.564,25.011 h3.05
  text "PCB厚度（mm）" at 40.511,20.566 h3.05
  text "筋厚" at 32.002,20.185 h3.05
  text "（余量）" at 30.732,17.137 h3.05
  text "0.6" at 40.511,17.01 h3.05
  text "0.8" at 46.598,17.01 h3.05
  text "1" at 54.124,17.01 h3.05
  text "1.2" at 58.799,17.01 h3.05
  text "1.6" at 64.895,17.01 h3.05
  text "2" at 72.134,17.01 h3.05
  text "2.5" at 77.072,17.01 h3.05
  text "3" at 84.326,17.01 h3.05
  text "0.16" at 39.753,13.517 h3.05
  text "0.2" at 46.611,13.517 h3.05
  text "0.3" at 52.707,13.517 h3.05
  text "0.3" at 58.698,13.517 h3.05
  text "0.4" at 64.807,13.517 h3.05
  text "0.5" at 70.999,13.517 h3.05
  text "0.5" at 77.091,13.517 h3.05
  text "最小值" at 30.605,13.454 h3.05
  text "0.5" at 83.158,13.454 h3.05
  text "0.32" at 39.763,10.025 h3.05
  text "0.4" at 46.604,10.025 h3.05
  text "0.45" at 51.941,10.025 h3.05
  text "0.5" at 58.691,10.025 h3.05
  text "0.6" at 64.87,10.025 h3.05
  text "0.7" at 71.006,10.025 h3.05
  text "0.8" at 77.095,10.025 h3.05
  text "0.8" at 83.186,10.025 h3.05
  text "最大值" at 30.605,9.898 h3.05
  text "6." at 26.262,5.58 h3.05
  text "PCB做完后，请高温烘烤进行应力释放，再整平（或重物压板烘烤），防止翘曲" at 29.564,5.58 h3.05
  text "我司生产使用无铅工艺制程" at 29.437,2.151 h3.05
  text "7." at 26.262,2.024 h3.05
Mechanical 15:
  lines w0.127: -135.81,5 -132,5 -132,8.886
Drill Drawing:
  text ".Legend" at 25.916,126.132 h1.52

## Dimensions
-256.15,169.999 to -256.15,0 on Mechanical 1
-262,8.85 to 0,8.85 on Mechanical 1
